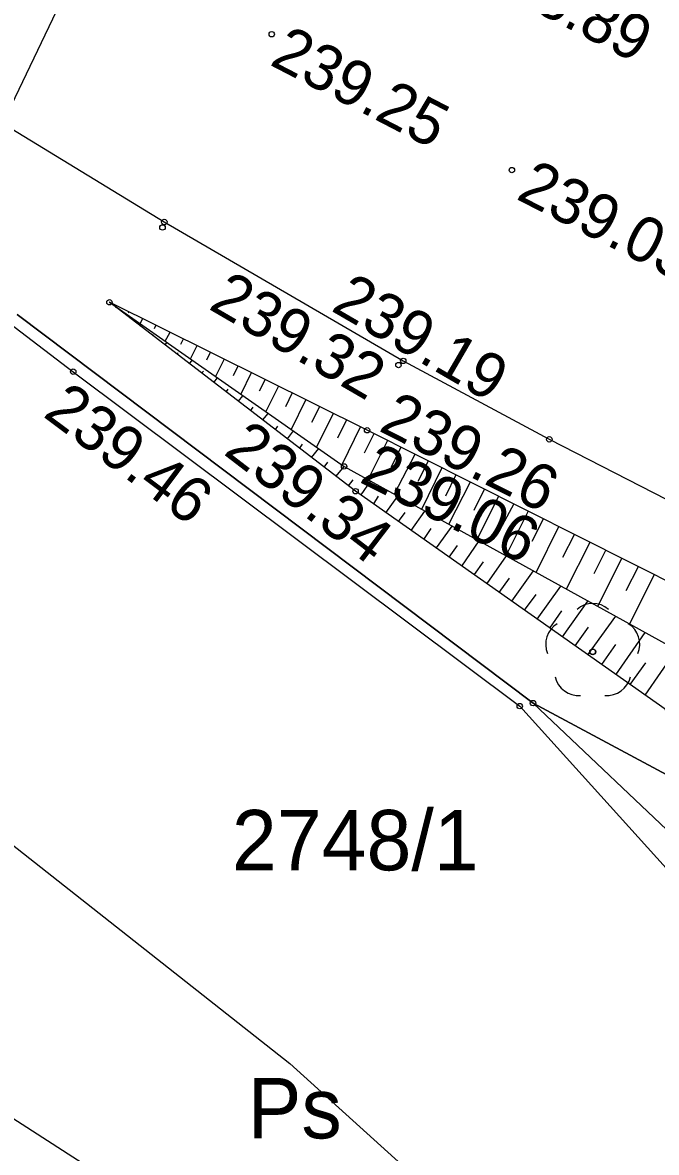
# Model space of a CAD drawing. Extents: x 6596400 to 6597200, y 5539751 to 5540251.
# Drawn here: x 6596673.62 to 6596684.12, y 5540092.08 to 5540110.79 of the extents above; entities that cross this region are included whole.
import ezdxf

# ---------------------------------------------------------------- set-up
doc = ezdxf.new("R2010")
doc.units = 0
for name, color, linetype in [('000 Inne (niezydentyfikowane)', 7, 'Continuous'), ('140-Punkty robocze', 7, 'Continuous'), ('203-punkt graniczny', 7, 'Continuous'), ('210-oznaczenie konturu użytku gruntowego', 7, 'Continuous'), ('211-numer działki ewidencyjnej', 7, 'Continuous'), ('217-kontur klasyfikacyjny', 7, 'Continuous'), ('218-kontur użytku gruntowego', 7, 'Continuous'), ('219-działka ewidencyjna', 7, 'Continuous'), ('drzewo liściaste', 7, 'Continuous'), ('jezdnia', 7, 'Continuous'), ('krawężnik', 7, 'Continuous'), ('Linia obszaru zagospodarowania terenu', 7, 'Continuous'), ('ogrodzenie trwałe', 7, 'Continuous'), ('pikieta sztuczna', 7, 'Continuous'), ('pikieta sztuczna-Atr2', 7, 'Continuous'), ('przewód elektroenergetyczny podziemny', 7, 'Continuous'), ('skarpa nieumocniona', 7, 'Continuous'), ('Zakres', 7, 'Continuous')]:
    doc.layers.add(name, color=color, linetype=linetype)

# ---------------------------------------------------------------- blocks, each defined once
blk = doc.blocks.new('203')
blk.add_circle((0, 0), 0.045)
blk = doc.blocks.new('OP021')
blk.add_circle((0, 0), 0.05)
for centre, start, end in [((0, 0.4), 49.272, 130.728), ((-0.38, 0.124), 121.308, 202.548), ((0.38, 0.124), 337.452, 58.692), ((-0.235, -0.324), 193.221, 274.871), ((0.235, -0.324), 265.129, 346.779)]:
    blk.add_arc(centre, 0.4, start, end)
blk = doc.blocks.new('PW01')
blk.add_circle((0, 0), 0.045)
blk = doc.blocks.new('PIKIETA')
blk.add_circle((0, 0), 0.045)

msp = doc.modelspace()

# ---------------------------------------------------------------- linework, layer by layer
at = {"layer": '000 Inne (niezydentyfikowane)'}
for p, q in [((6596675.17, 5540106.07), (6596675.17, 5540106.08)), ((6596675.37, 5540105.92), (6596675.38, 5540105.93)), ((6596675.58, 5540105.76), (6596675.59, 5540105.79)), ((6596675.78, 5540105.61), (6596675.79, 5540105.62)), ((6596675.98, 5540105.45), (6596676.01, 5540105.49)), ((6596676.18, 5540105.3), (6596676.2, 5540105.32)), ((6596676.39, 5540105.14), (6596676.43, 5540105.2)), ((6596676.59, 5540104.99), (6596676.62, 5540105.02)), ((6596676.79, 5540104.83), (6596676.85, 5540104.91)), ((6596677, 5540104.68), (6596677.03, 5540104.72)), ((6596677.2, 5540104.52), (6596677.27, 5540104.61)), ((6596677.4, 5540104.36), (6596677.44, 5540104.42)), ((6596677.6, 5540104.21), (6596677.69, 5540104.32)), ((6596677.81, 5540104.05), (6596677.85, 5540104.11)), ((6596678.01, 5540103.9), (6596678.11, 5540104.03)), ((6596678.21, 5540103.74), (6596678.26, 5540103.81)), ((6596678.41, 5540103.59), (6596678.53, 5540103.74)), ((6596678.62, 5540103.43), (6596678.68, 5540103.51)), ((6596678.82, 5540103.28), (6596678.95, 5540103.44)), ((6596679.02, 5540103.12), (6596679.1, 5540103.22)), ((6596679.23, 5540102.97), (6596679.39, 5540103.2)), ((6596679.44, 5540102.82), (6596679.52, 5540102.95)), ((6596679.64, 5540102.67), (6596679.84, 5540102.95)), ((6596679.85, 5540102.53), (6596679.96, 5540102.68)), ((6596680.06, 5540102.38), (6596680.29, 5540102.7)), ((6596680.27, 5540102.23), (6596680.39, 5540102.41)), ((6596680.48, 5540102.09), (6596680.74, 5540102.45)), ((6596680.9, 5540101.79), (6596681.19, 5540102.21)), ((6596680.69, 5540101.94), (6596680.83, 5540102.13)), ((6596681.11, 5540101.65), (6596681.26, 5540101.86)), ((6596681.32, 5540101.5), (6596681.64, 5540101.96)), ((6596681.73, 5540101.21), (6596682.09, 5540101.71)), ((6596681.52, 5540101.35), (6596681.69, 5540101.59)), ((6596682.15, 5540100.91), (6596682.54, 5540101.46)), ((6596681.94, 5540101.06), (6596682.13, 5540101.32)), ((6596682.57, 5540100.62), (6596682.99, 5540101.21)), ((6596682.36, 5540100.76), (6596682.56, 5540101.05)), ((6596682.99, 5540100.32), (6596683.45, 5540100.96)), ((6596682.78, 5540100.47), (6596683, 5540100.78)), ((6596683.45, 5540099.99), (6596683.94, 5540100.69)), ((6596683.22, 5540100.16), (6596683.45, 5540100.49)), ((6596683.94, 5540099.65), (6596684.46, 5540100.4)), ((6596683.69, 5540099.83), (6596683.95, 5540100.19))]:
    msp.add_line(p, q, dxfattribs=at)
for points in [[(6596675.16, 5540106.11), (6596675.15, 5540106.1)], [(6596675.38, 5540106), (6596675.37, 5540105.98)], [(6596675.61, 5540105.89), (6596675.57, 5540105.81)], [(6596675.83, 5540105.78), (6596675.8, 5540105.72)], [(6596676.06, 5540105.66), (6596675.98, 5540105.51)], [(6596676.28, 5540105.55), (6596676.24, 5540105.46)], [(6596676.51, 5540105.44), (6596676.4, 5540105.22)], [(6596676.73, 5540105.33), (6596676.67, 5540105.2)], [(6596676.96, 5540105.22), (6596676.82, 5540104.93)], [(6596677.19, 5540105.1), (6596677.11, 5540104.94)], [(6596677.41, 5540104.99), (6596677.24, 5540104.64)], [(6596677.64, 5540104.88), (6596677.54, 5540104.69)], [(6596677.86, 5540104.77), (6596677.65, 5540104.35)], [(6596678.09, 5540104.66), (6596677.98, 5540104.43)], [(6596678.31, 5540104.54), (6596678.07, 5540104.05)], [(6596678.54, 5540104.43), (6596678.41, 5540104.17)], [(6596678.77, 5540104.32), (6596678.49, 5540103.76)], [(6596678.99, 5540104.21), (6596678.84, 5540103.91)], [(6596679.22, 5540104.1), (6596678.91, 5540103.47)], [(6596679.44, 5540103.98), (6596679.28, 5540103.66)], [(6596679.67, 5540103.87), (6596679.34, 5540103.22)], [(6596679.89, 5540103.76), (6596679.73, 5540103.43)], [(6596680.12, 5540103.64), (6596679.78, 5540102.98)], [(6596680.34, 5540103.53), (6596680.17, 5540103.19)], [(6596680.57, 5540103.42), (6596680.23, 5540102.73)], [(6596680.8, 5540103.3), (6596680.63, 5540102.95)], [(6596681.04, 5540103.18), (6596680.68, 5540102.48)], [(6596681.27, 5540103.06), (6596681.1, 5540102.71)], [(6596681.51, 5540102.94), (6596681.15, 5540102.23)], [(6596681.76, 5540102.82), (6596681.57, 5540102.46)], [(6596682, 5540102.7), (6596681.63, 5540101.96)], [(6596682.25, 5540102.57), (6596682.06, 5540102.2)], [(6596682.5, 5540102.44), (6596682.13, 5540101.69)], [(6596682.76, 5540102.31), (6596682.57, 5540101.93)], [(6596683.02, 5540102.18), (6596682.63, 5540101.41)], [(6596683.28, 5540102.05), (6596683.09, 5540101.66)], [(6596683.55, 5540101.92), (6596683.15, 5540101.12)], [(6596683.82, 5540101.78), (6596683.62, 5540101.38)], [(6596684.09, 5540101.65), (6596683.68, 5540100.83)]]:
    msp.add_lwpolyline(points, dxfattribs=at)
at = {"layer": '217-kontur klasyfikacyjny'}
for points in [[(6596682.08, 5540099.52), (6596673.53, 5540105.96)], [(6596689.99, 5540092.03), (6596682.08, 5540099.52)]]:
    msp.add_lwpolyline(points, dxfattribs=at)
at = {"layer": '218-kontur użytku gruntowego'}
for points in [[(6596682.08, 5540099.52), (6596673.53, 5540105.96)], [(6596673.53, 5540105.96), (6596682.08, 5540099.52)], [(6596689.99, 5540092.03), (6596682.08, 5540099.52)], [(6596682.08, 5540099.52), (6596689.99, 5540092.03)], [(6596712.64, 5540083.14), (6596682.08, 5540099.52)], [(6596682.08, 5540099.52), (6596712.64, 5540083.14)]]:
    msp.add_lwpolyline(points, dxfattribs=at)
at = {"layer": '219-działka ewidencyjna'}
for points in [[(6596682.08, 5540099.52), (6596673.53, 5540105.96)], [(6596712.64, 5540083.14), (6596682.08, 5540099.52)], [(6596689.99, 5540092.03), (6596682.08, 5540099.52)]]:
    msp.add_lwpolyline(points, dxfattribs=at)
at = {"layer": 'jezdnia'}
msp.add_lwpolyline([(6596653.124, 5540120.82), (6596653.79, 5540120.41), (6596660.56, 5540116.72), (6596663.8, 5540114.85), (6596668, 5540112.34), (6596669.54, 5540111.42), (6596675.97, 5540107.49), (6596679.93, 5540105.19), (6596682.35, 5540103.89), (6596691.43, 5540099.24), (6596702.2, 5540094.56), (6596706.34, 5540093.02), (6596710.59, 5540091.59), (6596715.92, 5540090.16), (6596720.02, 5540089.23), (6596724.29, 5540088.47), (6596726.93, 5540087.96), (6596734.57, 5540086.51), (6596738.41, 5540085.75), (6596741.83, 5540085.11), (6596743.38, 5540084.84), (6596743.64, 5540085.7), (6596748.72, 5540084.9)], dxfattribs=at)
at = {"layer": 'krawężnik'}
msp.add_lwpolyline([(6596653.124, 5540120.82), (6596653.79, 5540120.41), (6596660.56, 5540116.72), (6596663.8, 5540114.85), (6596668, 5540112.34), (6596669.54, 5540111.42), (6596675.97, 5540107.49), (6596679.93, 5540105.19), (6596682.35, 5540103.89), (6596691.43, 5540099.24), (6596702.2, 5540094.56), (6596706.34, 5540093.02), (6596710.59, 5540091.59)], dxfattribs=at)
at = {"layer": 'Linia obszaru zagospodarowania terenu'}
msp.add_lwpolyline([(6596649.353, 5540112.883), (6596665.77, 5540102.07), (6596672.77, 5540097.71), (6596678.05, 5540093.55), (6596689.77, 5540082.95), (6596691.734, 5540080.864)], dxfattribs=at)
at = {"layer": 'ogrodzenie trwałe'}
msp.add_lwpolyline([(6596667.03, 5540110.64), (6596668.29, 5540109.72), (6596674.46, 5540105.01), (6596681.86, 5540099.47), (6596691.51, 5540088.79), (6596685.94, 5540084.598)], dxfattribs=at)
at = {"layer": 'przewód elektroenergetyczny podziemny'}
msp.add_lwpolyline([(6596685.598, 5540124.906), (6596682.98, 5540117.67), (6596678.46, 5540119.92), (6596672.31, 5540107.09), (6596661.92, 5540104.4), (6596656.89, 5540108.44), (6596653.516, 5540105.493)], dxfattribs=at)
at = {"layer": 'skarpa nieumocniona'}
for points in [[(6596678.95, 5540103.44), (6596684.48, 5540100.39), (6596690.52, 5540096.75), (6596701.2, 5540092.33), (6596705.49, 5540090.24), (6596709.93, 5540088.59), (6596713.91, 5540088.19), (6596713.79, 5540089.29), (6596710.4, 5540090.34), (6596706.06, 5540092.18), (6596701.79, 5540093.6), (6596690.99, 5540097.77), (6596684.6, 5540101.39), (6596679.33, 5540104.04), (6596675.06, 5540106.16)], [(6596678.95, 5540103.44), (6596684.48, 5540100.39), (6596690.52, 5540096.75), (6596701.2, 5540092.33), (6596705.49, 5540090.24), (6596709.93, 5540088.59), (6596713.91, 5540088.19), (6596713.79, 5540089.29), (6596710.4, 5540090.34), (6596706.06, 5540092.18), (6596701.79, 5540093.6), (6596690.99, 5540097.77), (6596684.6, 5540101.39), (6596679.33, 5540104.04), (6596675.06, 5540106.16)], [(6596678.95, 5540103.44), (6596684.48, 5540100.39), (6596694.1, 5540088.97), (6596698.32, 5540084.27), (6596700.74, 5540077.75), (6596705.03, 5540070.97), (6596697.73, 5540077), (6596697.69, 5540077.02), (6596691.51, 5540088.79), (6596684.27, 5540099.42), (6596679.14, 5540103.03), (6596675.06, 5540106.16)], [(6596678.95, 5540103.44), (6596684.48, 5540100.39), (6596694.1, 5540088.97), (6596698.32, 5540084.27), (6596700.74, 5540077.75), (6596705.03, 5540070.97), (6596697.73, 5540077), (6596697.69, 5540077.02), (6596691.51, 5540088.79), (6596684.27, 5540099.42), (6596679.14, 5540103.03), (6596675.06, 5540106.16)]]:
    msp.add_lwpolyline(points, close=True, dxfattribs=at)
at = {"layer": 'Zakres'}
msp.add_lwpolyline([(6596822.22, 5540097.5), (6596800.39, 5540105.4), (6596755.76, 5540121.45), (6596697.73, 5540120.74), (6596659.35, 5540133.92), (6596647.64, 5540109.28), (6596697.73, 5540077), (6596721.01, 5540057.77), (6596727.72, 5540045.95), (6596731.95, 5540033.61), (6596741.17, 5540031.18), (6596755.59, 5540029.2), (6596757.85, 5540044.22), (6596787.25, 5540055.04), (6596806.3, 5540048.33), (6596813.97, 5540042.6), (6596833.15, 5540068.58), (6596822.3, 5540077.75)], close=True, dxfattribs=at)

# ---------------------------------------------------------------- block references
at = {"layer": '140-Punkty robocze'}
for p in [(6596675.94, 5540107.4), (6596675.97, 5540107.49), (6596675.06, 5540106.16), (6596682.35, 5540103.89), (6596683.07, 5540100.37), (6596681.86, 5540099.47)]:
    msp.add_blockref('PIKIETA', p, dxfattribs=at)
at = {"layer": '203-punkt graniczny'}
msp.add_blockref('203', (6596682.08, 5540099.52), dxfattribs=at)
at = {"layer": 'drzewo liściaste'}
msp.add_blockref('OP021', (6596683.07, 5540100.37), dxfattribs=at)
at = {"layer": 'pikieta sztuczna'}
for p in [(6596677.75, 5540110.6), (6596681.73, 5540108.35), (6596679.93, 5540105.19), (6596674.46, 5540105.01), (6596679.85, 5540105.12), (6596679.33, 5540104.04), (6596678.95, 5540103.44), (6596679.14, 5540103.03)]:
    msp.add_blockref('PW01', p, dxfattribs=at)

# ---------------------------------------------------------------- texts
at = {"layer": '210-oznaczenie konturu użytku gruntowego'}
msp.add_text('Ps', height=1, dxfattribs=at).set_placement((6596677.35, 5540092.31))
at = {"layer": '211-numer działki ewidencyjnej'}
msp.add_text('2748/1', height=1, dxfattribs=at).set_placement((6596677.09, 5540096.75))
at = {"layer": 'pikieta sztuczna-Atr2'}
for s, rotation, p in [('238.89', 332.58, (6596681.065, 5540111.524)), ('239.25', 332.58, (6596677.695, 5540110.104)), ('239.03', 332.937, (6596681.779, 5540107.882)), ('239.32', 329.852, (6596676.683, 5540106.061)), ('239.19', 329.852, (6596678.713, 5540106.031)), ('239.46', 323.18, (6596673.941, 5540104.28)), ('239.26', 333.305, (6596679.503, 5540104.04)), ('239.34', 322.506, (6596676.933, 5540103.655)), ('239.06', 333.305, (6596679.183, 5540103.19))]:
    msp.add_text(s, height=0.75, rotation=rotation, dxfattribs=at).set_placement(p)

doc.saveas('drawing.dxf')
